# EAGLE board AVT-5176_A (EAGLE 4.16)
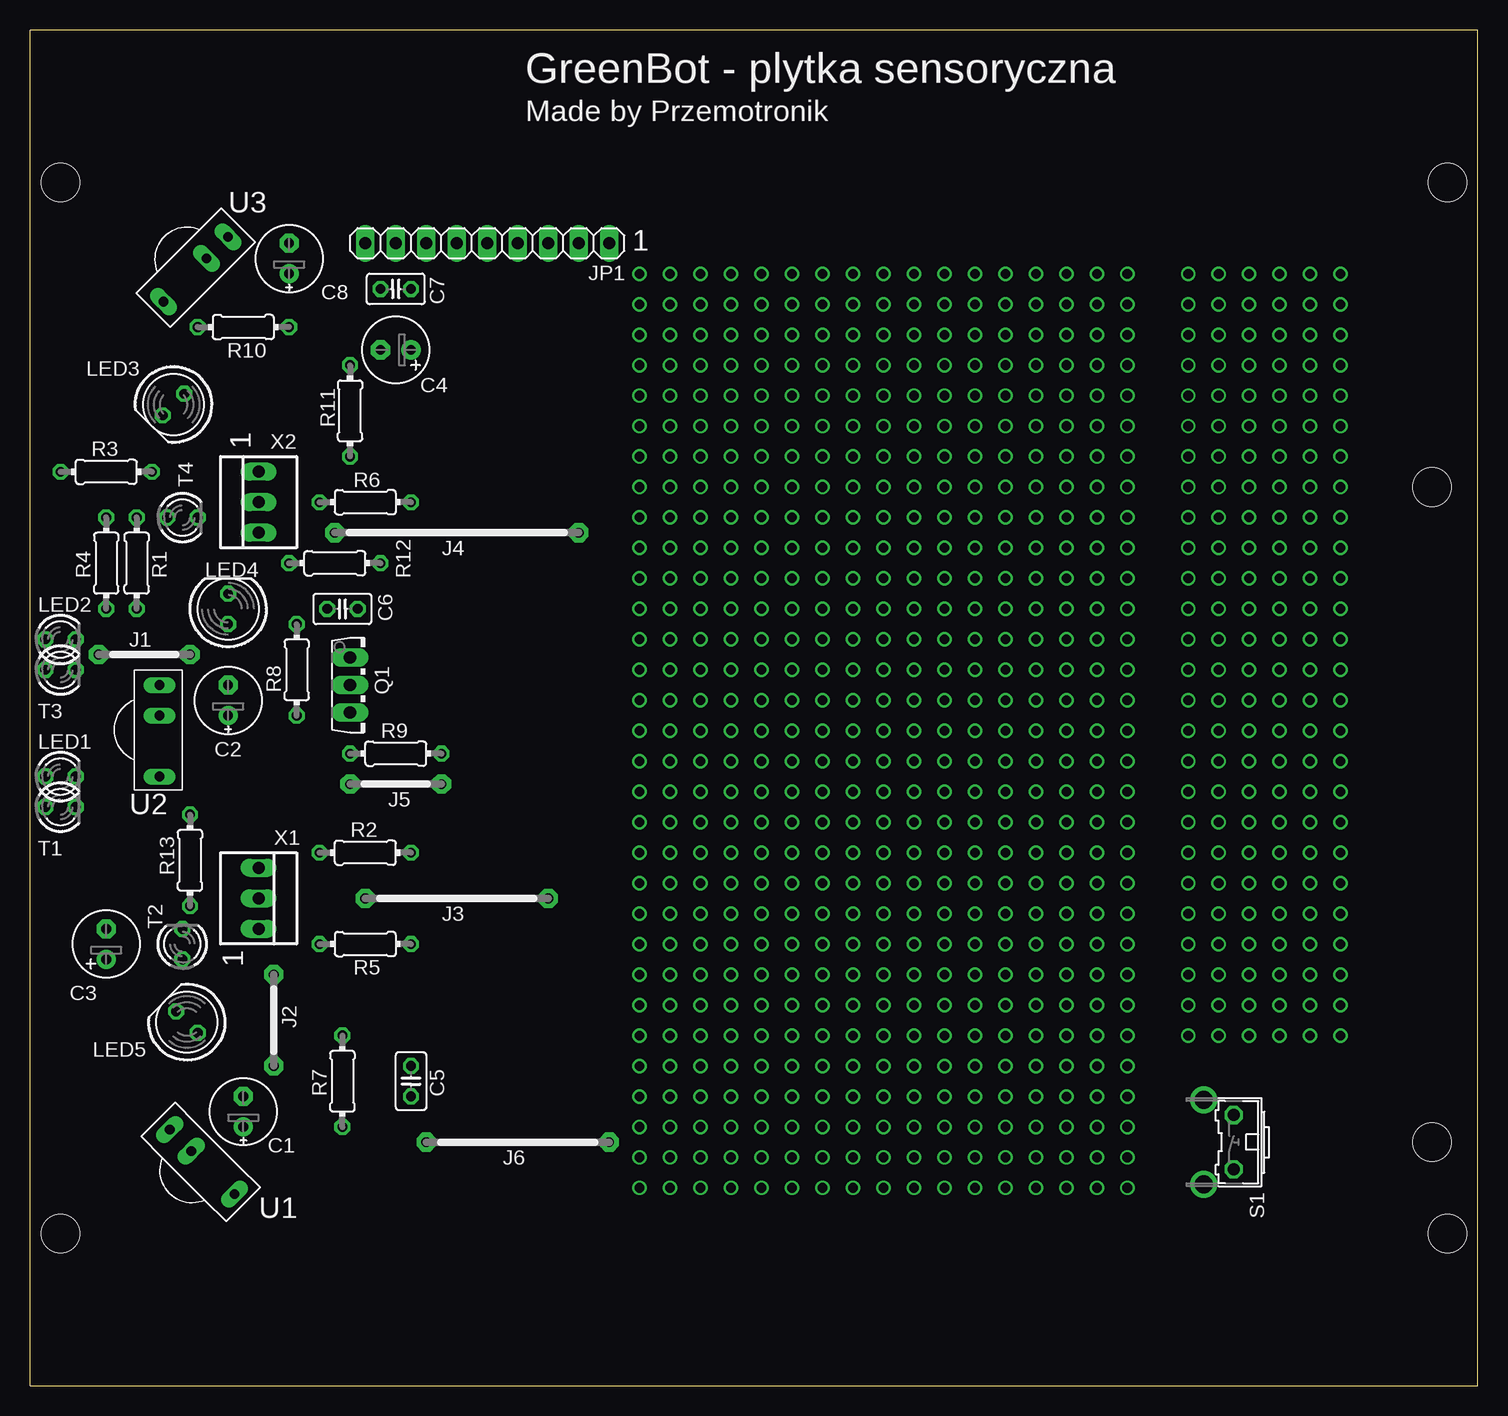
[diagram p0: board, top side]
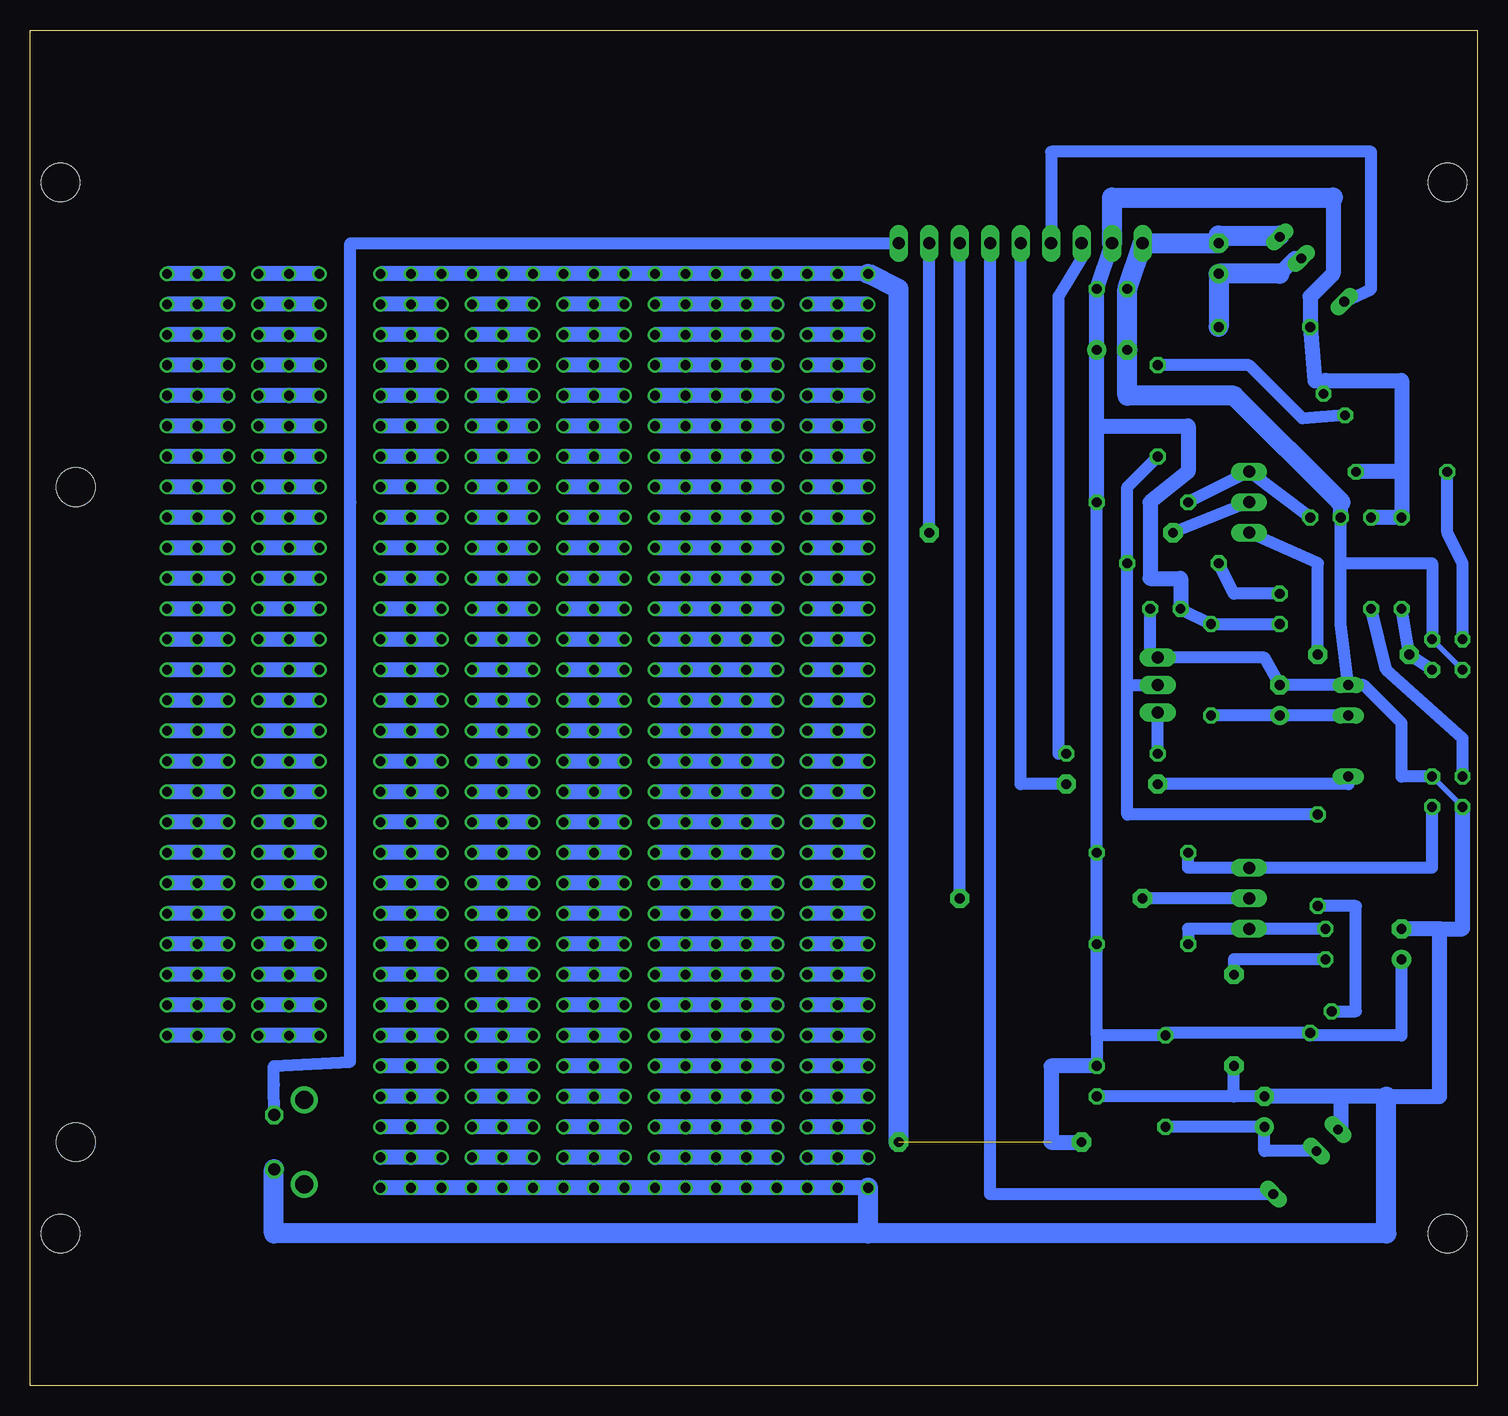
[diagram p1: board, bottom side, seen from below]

Size 120.65 x 113.03 mm. Coordinates in mm from the lower left corner, seen from the top.
Outline: 0,0 120.65,0 120.65,113.03 0,113.03 0,0
Copper layers (1*16): Top 0.035mm / dielectric 1.5mm / Bottom 0.035mm
Design rules "default": minimum track width 10mil, minimum drill 24mil, track to track 8mil, track to pad 8mil, pad to pad 8mil, via to via 8mil, smd to smd 8mil, copper to edge 40mil, drill to drill 8mil, minimum pad ring 10mil, minimum via ring 8mil, stop-mask expansion 4mil, vias tented up to drill 0mil, thermal gap 10mil
Holes 3.2 mm at 116.84,74.93 116.84,20.32 2.54,12.7 2.54,100.33 118.11,100.33 118.11,12.7

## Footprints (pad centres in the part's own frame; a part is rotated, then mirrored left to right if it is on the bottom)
E2,5-6E = drill 0.813 pad 1.575 round: + -1.27,0 | drill 0.813 pad 1.575 octagon: - 1.27,0
E2,5-6 = drill 0.813 pad 1.6 round: + -1.27,0 | drill 0.813 pad 1.6 octagon: - 1.27,0
C025-025X050 = drill 0.813 octagon: 1 -1.27,0; 2 1.27,0
07 = drill 0.813 pad 1.6 octagon: 1 -3.81,0; 2 3.81,0
15 = drill 0.813 pad 1.6 octagon: 1 -7.62,0; 2 7.62,0
20 = drill 0.813 pad 1.6 octagon: 1 -10.16,0; 2 10.16,0
1X09 = drill 1.016 long: 1 -10.16,0; 2 -7.62,0; 3 -5.08,0; 4 -2.54,0; 5 0,0; 6 2.54,0; 7 5.08,0; 8 7.62,0; 9 10.16,0
LED3MM = drill 0.813 octagon: A -1.27,0; K 1.27,0
LED5MM = drill 0.813 octagon: A -1.27,0; K 1.27,0
TO126AV = drill 1.016 long: B 2.286,-1.27; C 0,-1.27; E -2.286,-1.27
0204/7 = drill 0.813 octagon: 1 -3.81,0; 2 3.81,0
B3F-31XX = drill 1.016 octagon: 1 -2.261,-1.245; 2 2.261,-1.245 | drill 1.499 pad 2.159 round: 3 -3.505,1.245; 4 3.505,1.245
TSOP17XX = drill 0.813 long: GND -3.81,0; OUT 3.81,0; V+ -1.27,0
22-23-2031 = drill 1 long: 1 -2.54,0; 2 0,0; 3 2.54,0

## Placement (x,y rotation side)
C1  4,7u  [E2,5-6E]  17.78,22.86 90 top
C2  4,7uF  [E2,5-6E]  16.51,57.15 90 top
C3  100uF  [E2,5-6]  6.35,36.83 90 top
C4  100uF  [E2,5-6]  30.48,86.36 180 top
C5  100nF  [C025-025X050]  31.75,25.4 270 top
C6  100nF  [C025-025X050]  26.04,64.77 0 top
C7  100nF  [C025-025X050]  30.48,91.44 180 top
C8  4,7uF  [E2,5-6E]  21.59,93.98 90 top
J1  J7MM  [07]  9.53,60.96 0 top
J2  J7MM  [07]  20.32,30.48 90 top
J3  J15MM  [15]  35.56,40.64 180 top
J4  J20MM  [20]  35.56,71.12 180 top
J5  J7MM  [07]  30.48,50.16 0 top
J6  J15MM  [15]  40.64,20.32 180 top
JP1  [1X09]  38.1,95.25 180 top
LED1  QRD1114  [LED3MM]  2.54,50.8 0 top
LED2  QRD1114  [LED3MM]  2.54,62.23 0 top
LED3  LD271  [LED5MM]  11.96,81.81 225 top
LED4  LD271  [LED5MM]  16.51,64.77 90 top
LED5  LD271  [LED5MM]  13.07,30.33 135 top
Q1  BD135  [TO126AV]  27.94,58.42 270 top
R1  390R  [0204/7]  8.89,68.58 90 top
R2  10k  [0204/7]  27.94,44.45 0 top
R3  390R  [0204/7]  6.35,76.2 0 top
R4  10k  [0204/7]  6.35,68.58 90 top
R5  47k  [0204/7]  27.94,36.83 180 top
R6  47k  [0204/7]  27.94,73.66 180 top
R7  100R  [0204/7]  26.04,25.4 90 top
R8  100R  [0204/7]  22.23,59.69 90 top
R9  1k  [0204/7]  30.48,52.71 0 top
R10  100R  [0204/7]  17.78,88.27 180 top
R11  68R  [0204/7]  26.67,81.28 270 top
R12  68R  [0204/7]  25.4,68.58 0 top
R13  68R  [0204/7]  13.34,43.81 90 top
S1  [B3F-31XX]  99.06,20.32 90 top
T1  QRD1114  [LED3MM]  2.54,48.26 0 top
T2  SFH300 3/4  [LED3MM]  12.7,36.83 90 top
T3  QRD1114  [LED3MM]  2.54,59.69 0 top
T4  SFH300 3/4  [LED3MM]  12.7,72.39 0 top
U1  TSOP1736  [TSOP17XX]  14.34,18.68 315 top
U2  TSOP1736  [TSOP17XX]  10.79,54.61 270 top
U3  TSOP1736  [TSOP17XX]  13.82,93.08 225 top
X1  Goldpin 1x3  [22-23-2031]  19.05,40.64 270 top
X2  Goldpin 1x3  [22-23-2031]  19.05,73.66 90 top

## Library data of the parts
C1-C8 R1-R13 = rcl
J1-J6 = jumper
JP1 = pinhead
LED1 LED2 T1-T4 = vishay_tsal4400_bpw85c
LED3-LED5 = led
Q1 = transistor-power
S1 = switch-omron
U1-U3 = tsop
X1 X2 = con-molex

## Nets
+5V: C3.+ C4.+ C5.1 C6.1 C7.1 J6.1 J6.2 JP1.8 LED3.A LED4.A LED5.A R1.2 R2.2 R3.2 R4.2 R5.1 R6.1 R7.2 R8.2 R10.2
GND: C1.- C2.- C3.- C4.- C5.2 C6.2 C7.2 C8.- J2.1 JP1.9 LED1.K LED2.K Q1.E S1.1 T1.A T3.A T4.A U1.GND U2.GND U3.GND
N$1: J3.2 X1.2
N$3: J4.2 X2.2
N$4: JP1.1 S1.2
N$5: J5.1 U2.OUT
N$6: J2.2 T2.A
N$7: J1.2 X2.1
N$8: LED2.A R3.1
N$19: JP1.6 U3.OUT
N$23: J4.1 JP1.2
N$24: J3.1 JP1.3
N$40: LED1.A R1.1
N$51: J1.1 R4.1 T3.K
N$56: R2.1 T1.K X1.1
N$63: C8.+ R10.1 U3.V+
N$64: Q1.B R9.1
N$65: LED5.K R13.1
N$66: LED4.K R12.1
N$67: LED3.K R11.1
N$68: Q1.C R11.2 R12.2 R13.2
N$69: C1.+ R7.1 U1.V+
N$70: C2.+ R8.1 U2.V+
N$72: JP1.4 U1.OUT
N$73: J5.2 JP1.5
N$74: JP1.7 R9.2
N$75: R6.2 T4.K X2.3
N$76: R5.2 T2.K X1.3

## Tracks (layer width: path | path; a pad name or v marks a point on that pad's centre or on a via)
+5V  (via drill 0.8)  (1 unrouted)
  Bottom 1.016: 31.75,29.21 R7.2 26.04,29.43 LED5.A 13.97,29.21 6.35,29.21 C3.+ | 31.75,29.21 R5.1 R2.2 R6.1 | 31.75,29.21 C5.1 | LED4.A R8.2 C6.1 | 13.58,83.77 13.06,83.75 | 13.06,83.75 LED3.A | 12.7,83.82 12.7,83.75 13.06,83.75
  Bottom 1.27: JP1.8 C7.1 C4.+ 31.75,80.01 | R6.1 31.75,80.01 | 13.58,83.77 R10.2 13.97,90.8 12.06,92.71 12.06,99.06 | 6.35,76.2 R4.2 R1.2 | 6.35,76.2 R3.2 | C6.1 24.77,67.31 27.3,67.31 27.3,73.66 24.13,76.2 24.13,80.01 31.75,80.01 | 12.7,83.82 6.35,83.82 6.35,76.2 | J6.2 35.56,20.32 35.56,26.67 C5.1 | v91.44,92.71 v88.9,92.71 v86.36,92.71 v83.82,92.71 v81.28,92.71 v78.74,92.71 v76.2,92.71 v73.66,92.71 v71.12,92.71 v68.58,92.71 v66.04,92.71 v63.5,92.71 v60.96,92.71 v58.42,92.71 v55.88,92.71 v53.34,92.71 v50.8,92.71
  Bottom 1.676: 12.06,99.06 30.48,99.06 JP1.8 | J6.1 48.26,91.44 v50.8,92.71
GND  (via drill 0.8)
  Bottom 0.406: T1.A LED1.K | LED2.K T3.A
  Bottom 1.016: U2.GND C2.- 17.78,60.71 Q1.E 27.3,60.96 C6.2 | 11.43,21.37 U1.GND | C1.- 20.32,24.13 | 20.32,24.13 C5.2 | 100.33,18.06 S1.1 | LED2.K 3.81,68.58 11.43,68.58 | U2.GND 11.43,63.5 11.43,68.58 | 20.32,24.13 J2.1 | LED1.K 6.35,50.8 6.35,55.25 9.53,58.42 U2.GND | C8.- 21.59,95.88 | 16.51,95.88 U3.GND | 11.43,68.58 T4.A
  Bottom 1.27: 11.43,24.13 C1.- | 11.43,24.13 11.43,21.37 | 11.43,24.13 7.62,24.13 3.17,24.13 3.17,38.1 | T1.A 1.27,38.1 3.17,38.1 | T4.A 11.43,73.66 | 3.17,38.1 C3.- | v50.8,16.51 v53.34,16.51 v55.88,16.51 v58.42,16.51 v60.96,16.51 v63.5,16.51 v66.04,16.51 v68.58,16.51 v71.12,16.51 v73.66,16.51 v76.2,16.51 v78.74,16.51 v81.28,16.51 v83.82,16.51 v86.36,16.51 v88.9,16.51 v91.44,16.51
  Bottom 1.676: 100.33,18.06 100.33,12.7 50.8,12.7 | 50.8,12.7 7.62,12.7 7.62,24.13 | C8.- JP1.9 C7.2 C4.- 29.21,82.55 20.32,82.55 11.43,73.66 | 21.59,95.88 16.51,95.88 | 50.8,12.7 v50.8,16.51
N$1
  Bottom 1.016: X1.2 J3.2
N$2  (via drill 0.8)
  Bottom 1.27: v58.42,67.31 v60.96,67.31 v63.5,67.31 v66.04,67.31 v68.58,67.31
N$3
  Bottom 1.016: X2.2 J4.2
N$4
  Bottom 1.016: S1.2 100.33,25.12 100.33,26.67 93.98,27.03 93.98,73.66 93.95,73.66 93.95,95.25 JP1.1
N$5
  Bottom 1.016: U2.OUT 10.79,50.16 J5.1
N$6
  Bottom 1.016: T2.A 20.32,35.56 J2.2
N$7
  Bottom 1.016: J1.2 13.34,68.58 X2.1
N$8
  Bottom 1.016: LED2.A 1.27,68.58 2.54,71.12 R3.1
N$9  (via drill 0.8)
  Bottom 1.27: v71.12,67.31 v73.66,67.31 v76.2,67.31
N$10  (via drill 0.8)
  Bottom 1.27: v50.8,67.31 v53.34,67.31 v55.88,67.31
N$11  (via drill 0.8)
  Bottom 1.27: v58.42,64.77 v60.96,64.77 v63.5,64.77 v66.04,64.77 v68.58,64.77
N$12  (via drill 0.8)
  Bottom 1.27: v71.12,64.77 v73.66,64.77 v76.2,64.77
N$13  (via drill 0.8)
  Bottom 1.27: v50.8,64.77 v53.34,64.77 v55.88,64.77
N$14  (via drill 0.8)
  Bottom 1.27: v58.42,62.23 v60.96,62.23 v63.5,62.23 v66.04,62.23 v68.58,62.23
N$15  (via drill 0.8)
  Bottom 1.27: v71.12,62.23 v73.66,62.23 v76.2,62.23
N$16  (via drill 0.8)
  Bottom 1.27: v50.8,62.23 v53.34,62.23 v55.88,62.23
N$17  (via drill 0.8)
  Bottom 1.27: v58.42,59.69 v60.96,59.69 v63.5,59.69 v66.04,59.69 v68.58,59.69
N$18  (via drill 0.8)
  Bottom 1.27: v71.12,59.69 v73.66,59.69 v76.2,59.69
N$19
  Bottom 1.016: U3.OUT 8.89,91.44 8.89,102.87 35.56,102.87 JP1.6
N$20  (via drill 0.8)
  Bottom 1.27: v50.8,59.69 v53.34,59.69 v55.88,59.69
N$21  (via drill 0.8)
  Bottom 1.27: v58.42,57.15 v60.96,57.15 v63.5,57.15 v66.04,57.15 v68.58,57.15
N$22  (via drill 0.8)
  Bottom 1.27: v71.12,57.15 v73.66,57.15 v76.2,57.15
N$23
  Bottom 1.016: J4.1 JP1.2
N$24
  Bottom 1.016: J3.1 JP1.3
N$25  (via drill 0.8)
  Bottom 1.27: v50.8,57.15 v53.34,57.15 v55.88,57.15
N$26  (via drill 0.8)
  Bottom 1.27: v58.42,54.61 v60.96,54.61 v63.5,54.61 v66.04,54.61 v68.58,54.61
N$27  (via drill 0.8)
  Bottom 1.27: v71.12,54.61 v73.66,54.61 v76.2,54.61
N$28  (via drill 0.8)
  Bottom 1.27: v50.8,54.61 v53.34,54.61 v55.88,54.61
N$29  (via drill 0.8)
  Bottom 1.27: v58.42,52.07 v60.96,52.07 v63.5,52.07 v66.04,52.07 v68.58,52.07
N$30  (via drill 0.8)
  Bottom 1.27: v71.12,52.07 v73.66,52.07 v76.2,52.07
N$31  (via drill 0.8)
  Bottom 1.27: v50.8,52.07 v53.34,52.07 v55.88,52.07
N$32  (via drill 0.8)
  Bottom 1.27: v58.42,49.53 v60.96,49.53 v63.5,49.53 v66.04,49.53 v68.58,49.53
N$33  (via drill 0.8)
  Bottom 1.27: v71.12,49.53 v73.66,49.53 v76.2,49.53
N$34  (via drill 0.8)
  Bottom 1.27: v50.8,49.53 v53.34,49.53 v55.88,49.53
N$35  (via drill 0.8)
  Bottom 1.27: v58.42,46.99 v60.96,46.99 v63.5,46.99 v66.04,46.99 v68.58,46.99
N$36  (via drill 0.8)
  Bottom 1.27: v71.12,46.99 v73.66,46.99 v76.2,46.99
N$37  (via drill 0.8)
  Bottom 1.27: v50.8,46.99 v53.34,46.99 v55.88,46.99
N$38  (via drill 0.8)
  Bottom 1.27: v58.42,44.45 v60.96,44.45 v63.5,44.45 v66.04,44.45 v68.58,44.45
N$39  (via drill 0.8)
  Bottom 1.27: v71.12,44.45 v73.66,44.45 v76.2,44.45
N$40
  Bottom 1.016: R1.1 7.62,59.69 1.27,53.98 LED1.A
N$41  (via drill 0.8)
  Bottom 1.27: v50.8,44.45 v53.34,44.45 v55.88,44.45
N$42  (via drill 0.8)
  Bottom 1.27: v58.42,41.91 v60.96,41.91 v63.5,41.91 v66.04,41.91 v68.58,41.91
N$43  (via drill 0.8)
  Bottom 1.27: v71.12,41.91 v73.66,41.91 v76.2,41.91
N$44  (via drill 0.8)
  Bottom 1.27: v50.8,41.91 v53.34,41.91 v55.88,41.91
N$45  (via drill 0.8)
  Bottom 1.27: v58.42,39.37 v60.96,39.37 v63.5,39.37 v66.04,39.37 v68.58,39.37
N$46  (via drill 0.8)
  Bottom 1.27: v71.12,39.37 v73.66,39.37 v76.2,39.37
N$47  (via drill 0.8)
  Bottom 1.27: v50.8,39.37 v53.34,39.37 v55.88,39.37
N$48  (via drill 0.8)
  Bottom 1.27: v58.42,85.09 v60.96,85.09 v63.5,85.09 v66.04,85.09 v68.58,85.09
N$49  (via drill 0.8)
  Bottom 1.27: v71.12,85.09 v73.66,85.09 v76.2,85.09
N$50  (via drill 0.8)
  Bottom 1.27: v50.8,85.09 v53.34,85.09 v55.88,85.09
N$51
  Bottom 1.016: T3.K J1.1 R4.1
N$52  (via drill 0.8)
  Bottom 1.27: v58.42,80.01 v60.96,80.01 v63.5,80.01 v66.04,80.01 v68.58,80.01
N$53  (via drill 0.8)
  Bottom 1.27: v71.12,80.01 v73.66,80.01 v76.2,80.01
N$54  (via drill 0.8)
  Bottom 1.27: v50.8,80.01 v53.34,80.01 v55.88,80.01
N$55  (via drill 0.8)
  Bottom 1.27: v58.42,77.47 v60.96,77.47 v63.5,77.47 v66.04,77.47 v68.58,77.47
N$56
  Bottom 1.016: R2.1 24.13,43.18 X1.1 3.81,43.18 T1.K
N$57  (via drill 0.8)
  Bottom 1.27: v71.12,77.47 v73.66,77.47 v76.2,77.47
N$58  (via drill 0.8)
  Bottom 1.27: v50.8,77.47 v53.34,77.47 v55.88,77.47
N$59  (via drill 0.8)
  Bottom 1.27: v58.42,74.93 v60.96,74.93 v63.5,74.93 v66.04,74.93 v68.58,74.93
N$60  (via drill 0.8)
  Bottom 1.27: v71.12,74.93 v73.66,74.93 v76.2,74.93
N$61  (via drill 0.8)
  Bottom 1.27: v50.8,74.93 v53.34,74.93 v55.88,74.93
N$62  (via drill 0.8)
  Bottom 1.27: v58.42,72.39 v60.96,72.39 v63.5,72.39 v66.04,72.39 v68.58,72.39
N$63
  Bottom 1.016: U3.V+ 14.61,93.98 15.24,93.98
  Bottom 1.27: 15.24,93.98 16.51,92.71
  Bottom 1.676: 16.51,92.71 C8.+ R10.1
N$64
  Bottom 1.016: R9.1 Q1.B
N$65
  Bottom 1.016: LED5.K 10.16,31.22 10.16,40.01 R13.1
N$66
  Bottom 1.016: LED4.K 20.32,66.04 R12.1
N$67
  Bottom 1.016: R11.1 19.05,85.09 14.61,80.64 LED3.K
N$68
  Bottom 1.016: R13.2 29.21,47.62 29.21,58.42 | 29.21,58.42 Q1.C | 29.21,58.42 R12.2 29.21,74.93 R11.2
N$69
  Bottom 1.016: U1.V+ 17.78,19.58 C1.+ R7.1
N$70
  Bottom 1.016: U2.V+ C2.+ R8.1
N$71  (via drill 0.8)
  Bottom 1.27: v71.12,72.39 v73.66,72.39 v76.2,72.39
N$72
  Bottom 1.016: U1.OUT 40.64,15.98 JP1.4
N$73
  Bottom 1.016: JP1.5 38.1,50.16 J5.2
N$74
  Bottom 1.016: R9.2 34.92,52.71 34.92,90.8 33.02,93.98 JP1.7
N$75
  Bottom 1.016: T4.K X2.3 R6.2
N$76
  Bottom 1.016: R5.2 24.13,38.1 X1.3 T2.K
N$77  (via drill 0.8)
  Bottom 1.27: v50.8,72.39 v53.34,72.39 v55.88,72.39
N$78  (via drill 0.8)
  Bottom 1.27: v58.42,69.85 v60.96,69.85 v63.5,69.85 v66.04,69.85 v68.58,69.85
N$79  (via drill 0.8)
  Bottom 1.27: v71.12,69.85 v73.66,69.85 v76.2,69.85
N$80  (via drill 0.8)
  Bottom 1.27: v50.8,69.85 v53.34,69.85 v55.88,69.85
N$81  (via drill 0.8)
  Bottom 1.27: v58.42,36.83 v60.96,36.83 v63.5,36.83 v66.04,36.83 v68.58,36.83
N$82  (via drill 0.8)
  Bottom 1.27: v71.12,36.83 v73.66,36.83 v76.2,36.83
N$83  (via drill 0.8)
  Bottom 1.27: v50.8,36.83 v53.34,36.83 v55.88,36.83
N$84  (via drill 0.8)
  Bottom 1.27: v58.42,34.29 v60.96,34.29 v63.5,34.29 v66.04,34.29 v68.58,34.29
N$85  (via drill 0.8)
  Bottom 1.27: v71.12,34.29 v73.66,34.29 v76.2,34.29
N$86  (via drill 0.8)
  Bottom 1.27: v50.8,34.29 v53.34,34.29 v55.88,34.29
N$87  (via drill 0.8)
  Bottom 1.27: v58.42,31.75 v60.96,31.75 v63.5,31.75 v66.04,31.75 v68.58,31.75
N$88  (via drill 0.8)
  Bottom 1.27: v71.12,31.75 v73.66,31.75 v76.2,31.75
N$89  (via drill 0.8)
  Bottom 1.27: v50.8,31.75 v53.34,31.75 v55.88,31.75
N$90  (via drill 0.8)
  Bottom 1.27: v58.42,29.21 v60.96,29.21 v63.5,29.21 v66.04,29.21 v68.58,29.21
N$91  (via drill 0.8)
  Bottom 1.27: v71.12,29.21 v73.66,29.21 v76.2,29.21
N$92  (via drill 0.8)
  Bottom 1.27: v50.8,29.21 v53.34,29.21 v55.88,29.21
N$93  (via drill 0.8)
  Bottom 1.27: v58.42,26.67 v60.96,26.67 v63.5,26.67 v66.04,26.67 v68.58,26.67
N$94  (via drill 0.8)
  Bottom 1.27: v71.12,26.67 v73.66,26.67 v76.2,26.67
N$95  (via drill 0.8)
  Bottom 1.27: v50.8,26.67 v53.34,26.67 v55.88,26.67
N$96  (via drill 0.8)
  Bottom 1.27: v58.42,24.13 v60.96,24.13 v63.5,24.13 v66.04,24.13 v68.58,24.13
N$97  (via drill 0.8)
  Bottom 1.27: v71.12,24.13 v73.66,24.13 v76.2,24.13
N$98  (via drill 0.8)
  Bottom 1.27: v50.8,24.13 v53.34,24.13 v55.88,24.13
N$99  (via drill 0.8)
  Bottom 1.27: v58.42,21.59 v60.96,21.59 v63.5,21.59 v66.04,21.59 v68.58,21.59
N$100  (via drill 0.8)
  Bottom 1.27: v71.12,21.59 v73.66,21.59 v76.2,21.59
N$101  (via drill 0.8)
  Bottom 1.27: v50.8,21.59 v53.34,21.59 v55.88,21.59
N$102  (via drill 0.8)
  Bottom 1.27: v58.42,19.05 v60.96,19.05 v63.5,19.05 v66.04,19.05 v68.58,19.05
N$103  (via drill 0.8)
  Bottom 1.27: v71.12,19.05 v73.66,19.05 v76.2,19.05
N$104  (via drill 0.8)
  Bottom 1.27: v50.8,19.05 v53.34,19.05 v55.88,19.05
N$105  (via drill 0.8)
  Bottom 1.27: v58.42,82.55 v60.96,82.55 v63.5,82.55 v66.04,82.55 v68.58,82.55
N$106  (via drill 0.8)
  Bottom 1.27: v71.12,82.55 v73.66,82.55 v76.2,82.55
N$107  (via drill 0.8)
  Bottom 1.27: v50.8,82.55 v53.34,82.55 v55.88,82.55
N$108  (via drill 0.8)
  Bottom 1.27: v78.74,67.31 v81.28,67.31 v83.82,67.31
N$109  (via drill 0.8)
  Bottom 1.27: v78.74,64.77 v81.28,64.77 v83.82,64.77
N$110  (via drill 0.8)
  Bottom 1.27: v78.74,62.23 v81.28,62.23 v83.82,62.23
N$111  (via drill 0.8)
  Bottom 1.27: v78.74,59.69 v81.28,59.69 v83.82,59.69
N$112  (via drill 0.8)
  Bottom 1.27: v78.74,57.15 v81.28,57.15 v83.82,57.15
N$113  (via drill 0.8)
  Bottom 1.27: v78.74,54.61 v81.28,54.61 v83.82,54.61
N$114  (via drill 0.8)
  Bottom 1.27: v78.74,52.07 v81.28,52.07 v83.82,52.07
N$115  (via drill 0.8)
  Bottom 1.27: v78.74,49.53 v81.28,49.53 v83.82,49.53
N$116  (via drill 0.8)
  Bottom 1.27: v78.74,46.99 v81.28,46.99 v83.82,46.99
N$117  (via drill 0.8)
  Bottom 1.27: v78.74,44.45 v81.28,44.45 v83.82,44.45
N$118  (via drill 0.8)
  Bottom 1.27: v78.74,41.91 v81.28,41.91 v83.82,41.91
N$119  (via drill 0.8)
  Bottom 1.27: v78.74,39.37 v81.28,39.37 v83.82,39.37
N$120  (via drill 0.8)
  Bottom 1.27: v78.74,85.09 v81.28,85.09 v83.82,85.09
N$121  (via drill 0.8)
  Bottom 1.27: v78.74,80.01 v81.28,80.01 v83.82,80.01
N$122  (via drill 0.8)
  Bottom 1.27: v78.74,77.47 v81.28,77.47 v83.82,77.47
N$123  (via drill 0.8)
  Bottom 1.27: v78.74,74.93 v81.28,74.93 v83.82,74.93
N$124  (via drill 0.8)
  Bottom 1.27: v78.74,72.39 v81.28,72.39 v83.82,72.39
N$125  (via drill 0.8)
  Bottom 1.27: v78.74,69.85 v81.28,69.85 v83.82,69.85
N$126  (via drill 0.8)
  Bottom 1.27: v78.74,36.83 v81.28,36.83 v83.82,36.83
N$127  (via drill 0.8)
  Bottom 1.27: v78.74,34.29 v81.28,34.29 v83.82,34.29
N$128  (via drill 0.8)
  Bottom 1.27: v78.74,31.75 v81.28,31.75 v83.82,31.75
N$129  (via drill 0.8)
  Bottom 1.27: v78.74,29.21 v81.28,29.21 v83.82,29.21
N$130  (via drill 0.8)
  Bottom 1.27: v78.74,26.67 v81.28,26.67 v83.82,26.67
N$131  (via drill 0.8)
  Bottom 1.27: v78.74,24.13 v81.28,24.13 v83.82,24.13
N$132  (via drill 0.8)
  Bottom 1.27: v78.74,21.59 v81.28,21.59 v83.82,21.59
N$133  (via drill 0.8)
  Bottom 1.27: v78.74,19.05 v81.28,19.05 v83.82,19.05
N$134  (via drill 0.8)
  Bottom 1.27: v78.74,82.55 v81.28,82.55 v83.82,82.55
N$135  (via drill 0.8)
  Bottom 1.27: v86.36,67.31 v88.9,67.31 v91.44,67.31
N$136  (via drill 0.8)
  Bottom 1.27: v86.36,64.77 v88.9,64.77 v91.44,64.77
N$137  (via drill 0.8)
  Bottom 1.27: v86.36,62.23 v88.9,62.23 v91.44,62.23
N$138  (via drill 0.8)
  Bottom 1.27: v86.36,59.69 v88.9,59.69 v91.44,59.69
N$139  (via drill 0.8)
  Bottom 1.27: v86.36,57.15 v88.9,57.15 v91.44,57.15
N$140  (via drill 0.8)
  Bottom 1.27: v86.36,54.61 v88.9,54.61 v91.44,54.61
N$141  (via drill 0.8)
  Bottom 1.27: v86.36,52.07 v88.9,52.07 v91.44,52.07
N$142  (via drill 0.8)
  Bottom 1.27: v86.36,49.53 v88.9,49.53 v91.44,49.53
N$143  (via drill 0.8)
  Bottom 1.27: v86.36,46.99 v88.9,46.99 v91.44,46.99
N$144  (via drill 0.8)
  Bottom 1.27: v86.36,44.45 v88.9,44.45 v91.44,44.45
N$145  (via drill 0.8)
  Bottom 1.27: v86.36,41.91 v88.9,41.91 v91.44,41.91
N$146  (via drill 0.8)
  Bottom 1.27: v86.36,39.37 v88.9,39.37 v91.44,39.37
N$147  (via drill 0.8)
  Bottom 1.27: v86.36,85.09 v88.9,85.09 v91.44,85.09
N$148  (via drill 0.8)
  Bottom 1.27: v86.36,80.01 v88.9,80.01 v91.44,80.01
N$149  (via drill 0.8)
  Bottom 1.27: v86.36,77.47 v88.9,77.47 v91.44,77.47
N$150  (via drill 0.8)
  Bottom 1.27: v86.36,74.93 v88.9,74.93 v91.44,74.93
N$151  (via drill 0.8)
  Bottom 1.27: v86.36,72.39 v88.9,72.39 v91.44,72.39
N$152  (via drill 0.8)
  Bottom 1.27: v86.36,69.85 v88.9,69.85 v91.44,69.85
N$153  (via drill 0.8)
  Bottom 1.27: v86.36,36.83 v88.9,36.83 v91.44,36.83
N$154  (via drill 0.8)
  Bottom 1.27: v86.36,34.29 v88.9,34.29 v91.44,34.29
N$155  (via drill 0.8)
  Bottom 1.27: v86.36,31.75 v88.9,31.75 v91.44,31.75
N$156  (via drill 0.8)
  Bottom 1.27: v86.36,29.21 v88.9,29.21 v91.44,29.21
N$157  (via drill 0.8)
  Bottom 1.27: v86.36,26.67 v88.9,26.67 v91.44,26.67
N$158  (via drill 0.8)
  Bottom 1.27: v86.36,24.13 v88.9,24.13 v91.44,24.13
N$159  (via drill 0.8)
  Bottom 1.27: v86.36,21.59 v88.9,21.59 v91.44,21.59
N$160  (via drill 0.8)
  Bottom 1.27: v86.36,19.05 v88.9,19.05 v91.44,19.05
N$161  (via drill 0.8)
  Bottom 1.27: v86.36,82.55 v88.9,82.55 v91.44,82.55
N$162  (via drill 0.8)
  Bottom 1.27: v96.52,85.09 v99.06,85.09 v101.6,85.09
N$163  (via drill 0.8)
  Bottom 1.27: v96.52,82.55 v99.06,82.55 v101.6,82.55
N$164  (via drill 0.8)
  Bottom 1.27: v96.52,80.01 v99.06,80.01 v101.6,80.01
N$165  (via drill 0.8)
  Bottom 1.27: v96.52,77.47 v99.06,77.47 v101.6,77.47
N$166  (via drill 0.8)
  Bottom 1.27: v96.52,74.93 v99.06,74.93 v101.6,74.93
N$167  (via drill 0.8)
  Bottom 1.27: v96.52,72.39 v99.06,72.39 v101.6,72.39
N$168  (via drill 0.8)
  Bottom 1.27: v96.52,69.85 v99.06,69.85 v101.6,69.85
N$169  (via drill 0.8)
  Bottom 1.27: v96.52,67.31 v99.06,67.31 v101.6,67.31
N$170  (via drill 0.8)
  Bottom 1.27: v96.52,64.77 v99.06,64.77 v101.6,64.77
N$171  (via drill 0.8)
  Bottom 1.27: v96.52,62.23 v99.06,62.23 v101.6,62.23
N$172  (via drill 0.8)
  Bottom 1.27: v96.52,59.69 v99.06,59.69 v101.6,59.69
N$173  (via drill 0.8)
  Bottom 1.27: v96.52,57.15 v99.06,57.15 v101.6,57.15
N$174  (via drill 0.8)
  Bottom 1.27: v58.42,90.17 v60.96,90.17 v63.5,90.17 v66.04,90.17 v68.58,90.17
N$175  (via drill 0.8)
  Bottom 1.27: v71.12,90.17 v73.66,90.17 v76.2,90.17
N$176  (via drill 0.8)
  Bottom 1.27: v50.8,90.17 v53.34,90.17 v55.88,90.17
N$177  (via drill 0.8)
  Bottom 1.27: v96.52,92.71 v99.06,92.71 v101.6,92.71
N$178  (via drill 0.8)
  Bottom 1.27: v96.52,90.17 v99.06,90.17 v101.6,90.17
N$179  (via drill 0.8)
  Bottom 1.27: v96.52,87.63 v99.06,87.63 v101.6,87.63
N$180  (via drill 0.8)
  Bottom 1.27: v96.52,54.61 v99.06,54.61 v101.6,54.61
N$181  (via drill 0.8)
  Bottom 1.27: v96.52,52.07 v99.06,52.07 v101.6,52.07
N$182  (via drill 0.8)
  Bottom 1.27: v96.52,49.53 v99.06,49.53 v101.6,49.53
N$183  (via drill 0.8)
  Bottom 1.27: v96.52,46.99 v99.06,46.99 v101.6,46.99
N$184  (via drill 0.8)
  Bottom 1.27: v96.52,44.45 v99.06,44.45 v101.6,44.45
N$185  (via drill 0.8)
  Bottom 1.27: v96.52,41.91 v99.06,41.91 v101.6,41.91
N$186  (via drill 0.8)
  Bottom 1.27: v96.52,39.37 v99.06,39.37 v101.6,39.37
N$187  (via drill 0.8)
  Bottom 1.27: v96.52,36.83 v99.06,36.83 v101.6,36.83
N$188  (via drill 0.8)
  Bottom 1.27: v96.52,34.29 v99.06,34.29 v101.6,34.29
N$189  (via drill 0.8)
  Bottom 1.27: v104.14,85.09 v106.68,85.09 v109.22,85.09
N$190  (via drill 0.8)
  Bottom 1.27: v104.14,82.55 v106.68,82.55 v109.22,82.55
N$191  (via drill 0.8)
  Bottom 1.27: v104.14,80.01 v106.68,80.01 v109.22,80.01
N$192  (via drill 0.8)
  Bottom 1.27: v104.14,77.47 v106.68,77.47 v109.22,77.47
N$193  (via drill 0.8)
  Bottom 1.27: v104.14,74.93 v106.68,74.93 v109.22,74.93
N$194  (via drill 0.8)
  Bottom 1.27: v104.14,72.39 v106.68,72.39 v109.22,72.39
N$195  (via drill 0.8)
  Bottom 1.27: v104.14,69.85 v106.68,69.85 v109.22,69.85
N$196  (via drill 0.8)
  Bottom 1.27: v104.14,67.31 v106.68,67.31 v109.22,67.31
N$197  (via drill 0.8)
  Bottom 1.27: v104.14,64.77 v106.68,64.77 v109.22,64.77
N$198  (via drill 0.8)
  Bottom 1.27: v104.14,62.23 v106.68,62.23 v109.22,62.23
N$199  (via drill 0.8)
  Bottom 1.27: v104.14,59.69 v106.68,59.69 v109.22,59.69
N$200  (via drill 0.8)
  Bottom 1.27: v104.14,57.15 v106.68,57.15 v109.22,57.15
N$201  (via drill 0.8)
  Bottom 1.27: v58.42,87.63 v60.96,87.63 v63.5,87.63 v66.04,87.63 v68.58,87.63
N$202  (via drill 0.8)
  Bottom 1.27: v71.12,87.63 v73.66,87.63 v76.2,87.63
N$203  (via drill 0.8)
  Bottom 1.27: v50.8,87.63 v53.34,87.63 v55.88,87.63
N$204  (via drill 0.8)
  Bottom 1.27: v104.14,92.71 v106.68,92.71 v109.22,92.71
N$205  (via drill 0.8)
  Bottom 1.27: v104.14,90.17 v106.68,90.17 v109.22,90.17
N$206  (via drill 0.8)
  Bottom 1.27: v104.14,87.63 v106.68,87.63 v109.22,87.63
N$207  (via drill 0.8)
  Bottom 1.27: v104.14,54.61 v106.68,54.61 v109.22,54.61
N$208  (via drill 0.8)
  Bottom 1.27: v104.14,52.07 v106.68,52.07 v109.22,52.07
N$209  (via drill 0.8)
  Bottom 1.27: v104.14,49.53 v106.68,49.53 v109.22,49.53
N$210  (via drill 0.8)
  Bottom 1.27: v104.14,46.99 v106.68,46.99 v109.22,46.99
N$211  (via drill 0.8)
  Bottom 1.27: v104.14,44.45 v106.68,44.45 v109.22,44.45
N$212  (via drill 0.8)
  Bottom 1.27: v104.14,41.91 v106.68,41.91 v109.22,41.91
N$213  (via drill 0.8)
  Bottom 1.27: v104.14,39.37 v106.68,39.37 v109.22,39.37
N$214  (via drill 0.8)
  Bottom 1.27: v104.14,36.83 v106.68,36.83 v109.22,36.83
N$215  (via drill 0.8)
  Bottom 1.27: v104.14,34.29 v106.68,34.29 v109.22,34.29
N$216  (via drill 0.8)
  Bottom 1.27: v78.74,90.17 v81.28,90.17 v83.82,90.17
N$217  (via drill 0.8)
  Bottom 1.27: v78.74,87.63 v81.28,87.63 v83.82,87.63
N$218  (via drill 0.8)
  Bottom 1.27: v86.36,90.17 v88.9,90.17 v91.44,90.17
N$219  (via drill 0.8)
  Bottom 1.27: v86.36,87.63 v88.9,87.63 v91.44,87.63
N$220  (via drill 0.8)
  Bottom 1.27: v96.52,31.75 v99.06,31.75 v101.6,31.75
N$221  (via drill 0.8)
  Bottom 1.27: v96.52,29.21 v99.06,29.21 v101.6,29.21
N$223  (via drill 0.8)
  Bottom 1.27: v104.14,31.75 v106.68,31.75 v109.22,31.75
N$224  (via drill 0.8)
  Bottom 1.27: v104.14,29.21 v106.68,29.21 v109.22,29.21

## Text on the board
tPlace: GreenBot - plytka sensoryczna | Made by Przemotronik
tNames: U3 | 1 | 1 | U2 | 1 | U1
